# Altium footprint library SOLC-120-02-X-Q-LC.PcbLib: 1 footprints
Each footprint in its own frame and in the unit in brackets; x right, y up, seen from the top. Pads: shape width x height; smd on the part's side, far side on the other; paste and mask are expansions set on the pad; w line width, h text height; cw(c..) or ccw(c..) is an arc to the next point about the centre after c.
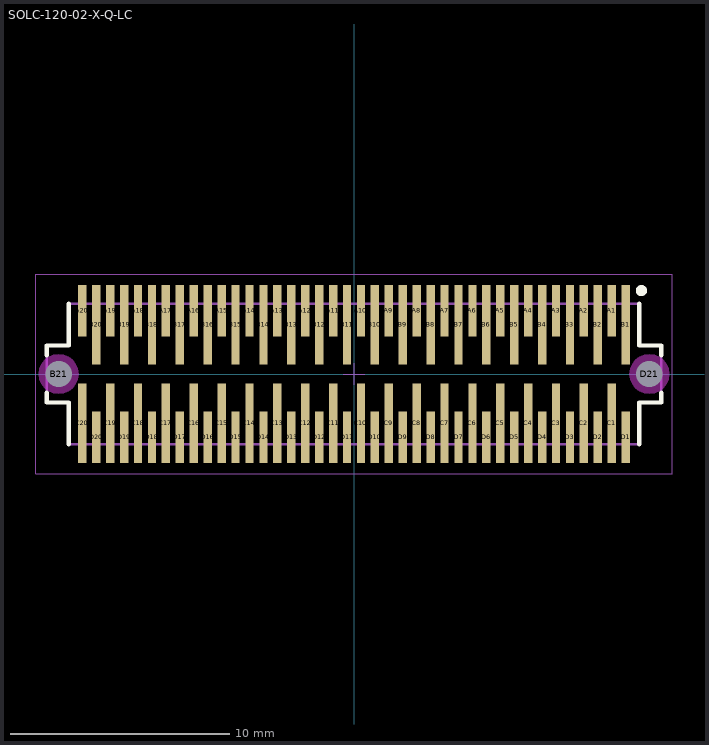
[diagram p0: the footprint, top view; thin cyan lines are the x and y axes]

## SOLC-120-02-X-Q-LC [mm] "1.27mm pitch, 80 pin, socket strip; 4 rows, w/locking clips, SMT"
height 4.62
pads (82):
  rect 0.38x2.36 smd mask+0: A1(11.747,2.885) A2(10.477,2.885) A3(9.207,2.885) A4(7.938,2.885) A5(6.667,2.885) A6(5.397,2.885) A7(4.127,2.885) A8(2.857,2.885) A9(1.587,2.885) A10(0.318,2.885) A11(-0.953,2.885) A12(-2.222,2.885) A13(-3.492,2.885) A14(-4.763,2.885) A15(-6.032,2.885) A16(-7.302,2.885) A17(-8.572,2.885) A18(-9.842,2.885) A19(-11.112,2.885) A20(-12.383,2.885) D1(12.383,-2.885) D2(11.112,-2.885) D3(9.842,-2.885) D4(8.572,-2.885) D5(7.302,-2.885) D6(6.032,-2.885) D7(4.763,-2.885) D8(3.492,-2.885) D9(2.222,-2.885) D10(0.953,-2.885) D11(-0.318,-2.885) D12(-1.587,-2.885) D13(-2.857,-2.885) D14(-4.127,-2.885) D15(-5.397,-2.885) D16(-6.667,-2.885) D17(-7.938,-2.885) D18(-9.207,-2.885) D19(-10.477,-2.885) D20(-11.747,-2.885)
  rect 0.38x3.63 smd mask+0: B1(12.383,2.25) B2(11.112,2.25) B3(9.842,2.25) B4(8.572,2.25) B5(7.302,2.25) B6(6.032,2.25) B7(4.763,2.25) B8(3.492,2.25) B9(2.222,2.25) B10(0.953,2.25) B11(-0.318,2.25) B12(-1.587,2.25) B13(-2.857,2.25) B14(-4.127,2.25) B15(-5.397,2.25) B16(-6.667,2.25) B17(-7.938,2.25) B18(-9.207,2.25) B19(-10.477,2.25) B20(-11.747,2.25) C1(11.747,-2.25) C2(10.477,-2.25) C3(9.207,-2.25) C4(7.938,-2.25) C5(6.667,-2.25) C6(5.397,-2.25) C7(4.127,-2.25) C8(2.857,-2.25) C9(1.587,-2.25) C10(0.318,-2.25) C11(-0.953,-2.25) C12(-2.222,-2.25) C13(-3.492,-2.25) C14(-4.763,-2.25) C15(-6.032,-2.25) C16(-7.302,-2.25) C17(-8.572,-2.25) C18(-9.842,-2.25) C19(-11.112,-2.25) C20(-12.383,-2.25)
  round 1 hole 1.2 unplated mask+0: B21(-13.462,0) D21(13.462,0)
Top Overlay:
  circle w0.25: c13.1,3.8 r0.125
  lines w0.2: -14,-0.85 -14,-1.3 -13,-1.3 -13,-3.2 ; -14,0.85 -14,1.3 -13,1.3 -13,3.2 ; 13,-3.2 13,-1.3 14,-1.3 14,-0.85 ; 13,3.2 13,1.3 14,1.3 14,0.85
Keep-Out Layer:
  pour cut-out: 14.37,0 14.339,0.235 14.248,0.454 14.104,0.642 13.916,0.786 13.697,0.877 13.462,0.908 13.227,0.877 13.008,0.786 12.82,0.642 12.676,0.454 12.585,0.235 12.554,0 12.585,-0.235 12.676,-0.454 12.82,-0.642 13.008,-0.786 13.227,-0.877 13.462,-0.908 13.697,-0.877 13.916,-0.786 14.104,-0.642 14.248,-0.454 14.339,-0.235
  pour cut-out: -12.554,0 -12.585,0.235 -12.676,0.454 -12.82,0.642 -13.008,0.786 -13.227,0.877 -13.462,0.908 -13.697,0.877 -13.916,0.786 -14.104,0.642 -14.248,0.454 -14.339,0.235 -14.37,0 -14.339,-0.235 -14.248,-0.454 -14.104,-0.642 -13.916,-0.786 -13.697,-0.877 -13.462,-0.908 -13.227,-0.877 -13.008,-0.786 -12.82,-0.642 -12.676,-0.454 -12.585,-0.235
Mechanical 12:
  lines w0.001: -14,-1.3 -14,1.3 -13,1.3 -13,3.2 13,3.2 13,1.3 14,1.3 14,-1.3 13,-1.3 13,-3.2 -13,-3.2 -13,-1.3 -14,-1.3
Mechanical 13:
  lines w0.1: -14,-1.3 -14,1.3 -13,1.3 -13,3.2 13,3.2 13,1.3 14,1.3 14,-1.3 13,-1.3 13,-3.2 -13,-3.2 -13,-1.3 -14,-1.3
  text ".Designator" at 0,-0.127 h1.52
Mechanical 15:
  lines w0.05: -0.5,0 0.5,0 ; 0,-0.5 0,0.5 ; -14.5,-4.55 -14.5,4.55 14.5,4.55 14.5,-4.55 -14.5,-4.55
